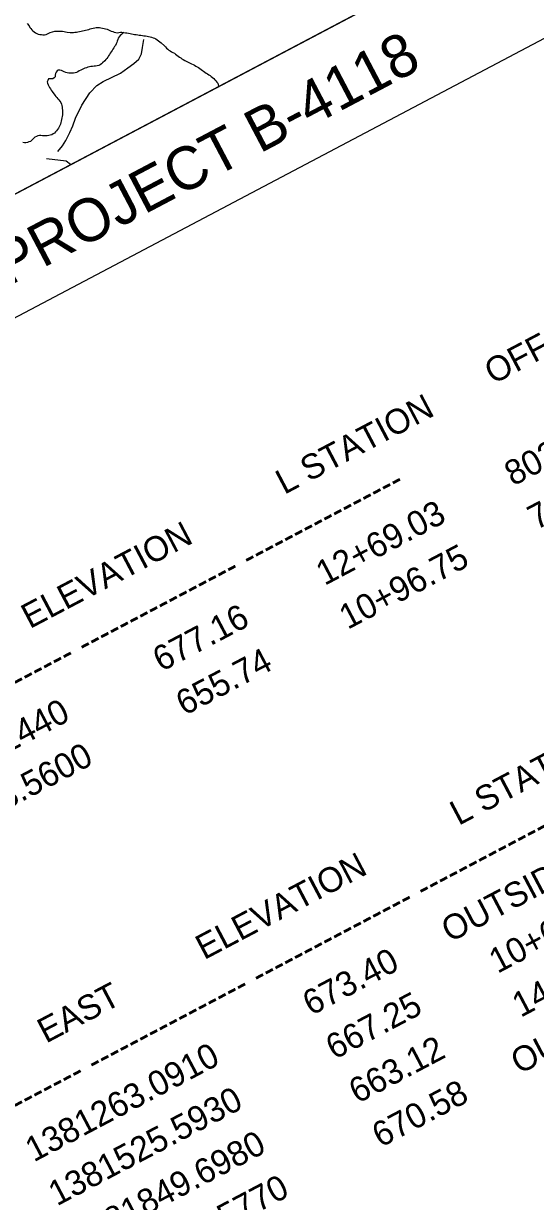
# Model space of a CAD drawing. Extents: x 1379448 to 1382868, y 593769 to 596827.
# Drawn here: x 1380243 to 1380457.9, y 594832.7 to 595326.7 of the extents above; entities that cross this region are included whole.
import ezdxf

# ---------------------------------------------------------------- set-up
doc = ezdxf.new("R2010")
doc.units = 0
for name, color, linetype in [('CTL Sheet Text', 7, 'Continuous'), ('Old_Level_1', 7, 'Continuous'), ('Old_Level_32', 7, 'Continuous'), ('Old_Level_35', 7, 'Continuous'), ('Old_Level_59', 7, 'Continuous'), ('Old_Level_62', 7, 'Continuous')]:
    doc.layers.add(name, color=color, linetype=linetype)

msp = doc.modelspace()

# ---------------------------------------------------------------- linework, layer by layer
at = {"layer": 'Old_Level_1'}
msp.add_line((1379782.59, 595014.48), (1380447.79, 595365.17), dxfattribs=at)
msp.add_lwpolyline([(1379782.59, 595014.48), (1380447.79, 595365.17), (1380469.23, 595324.5), (1379804.02, 594973.82)], close=True, dxfattribs=at)
at = {"layer": 'Old_Level_32'}
msp.add_lwpolyline([(1380262.66, 595267.57), (1380260.81, 595268.98), (1380252.6, 595269.97)], dxfattribs=at)
at = {"layer": 'Old_Level_35'}
msp.add_lwpolyline([(1380257.31, 595273.11), (1380259.38, 595275.46), (1380260.68, 595277.67), (1380262.44, 595281.04), (1380263.65, 595283.75), (1380264.74, 595286.99), (1380267.38, 595292.47), (1380270.76, 595297.66), (1380273.73, 595300.77), (1380276.44, 595302.45), (1380283.69, 595305.86), (1380286.74, 595308.2), (1380289.22, 595310), (1380291.42, 595311.73), (1380292.55, 595314.03), (1380292.98, 595316.7), (1380293.52, 595319.99)], dxfattribs=at)
at = {"layer": 'Old_Level_59'}
for points in [[(1380244.56, 595326.74), (1380245.35, 595325.71), (1380245.65, 595325.12), (1380246.05, 595324.6), (1380246.46, 595324.09), (1380246.91, 595323.6), (1380247.4, 595323.18), (1380247.97, 595322.83), (1380248.55, 595322.55), (1380249.18, 595322.31), (1380249.81, 595322.16), (1380250.47, 595322.08), (1380251.12, 595322.03), (1380251.78, 595322), (1380252.42, 595322.12), (1380253.02, 595322.4), (1380253.6, 595322.71), (1380254.19, 595323), (1380256.05, 595323.55), (1380256.71, 595323.58), (1380257.36, 595323.58), (1380258.02, 595323.56), (1380258.68, 595323.51), (1380259.34, 595323.46), (1380259.99, 595323.38), (1380260.63, 595323.26), (1380261.28, 595323.15), (1380262.59, 595322.97), (1380263.24, 595322.91), (1380263.9, 595322.95), (1380264.54, 595323.05), (1380265.19, 595323.16), (1380265.83, 595323.27), (1380266.48, 595323.4), (1380267.12, 595323.54), (1380267.76, 595323.68), (1380268.4, 595323.83), (1380269.04, 595323.97), (1380270.33, 595324.27), (1380270.94, 595324.49), (1380271.55, 595324.69), (1380272.2, 595324.82), (1380272.85, 595324.92), (1380273.51, 595325), (1380274.16, 595325.04)], [(1380274.16, 595325.04), (1380274.81, 595325.02), (1380275.46, 595324.95), (1380276.12, 595324.84), (1380276.76, 595324.7), (1380277.4, 595324.54), (1380278.02, 595324.32), (1380278.63, 595324.09), (1380279.2, 595323.77), (1380279.82, 595323.54), (1380280.44, 595323.33), (1380281.07, 595323.14), (1380281.71, 595322.99), (1380282.36, 595322.88), (1380282.99, 595322.95), (1380283.63, 595323.06), (1380284.29, 595323.05), (1380285.08, 595322.89)], [(1380285.08, 595322.89), (1380285.74, 595322.87), (1380286.39, 595322.77), (1380287.03, 595322.63), (1380287.67, 595322.48), (1380288.32, 595322.35), (1380288.96, 595322.24), (1380289.61, 595322.14), (1380290.26, 595322.05), (1380290.91, 595321.96), (1380291.56, 595321.87), (1380292.22, 595321.79), (1380292.86, 595321.69), (1380293.51, 595321.6), (1380294.17, 595321.5), (1380294.81, 595321.39), (1380295.45, 595321.28), (1380296.1, 595321.13), (1380296.73, 595320.95), (1380297.36, 595320.75), (1380297.97, 595320.52), (1380298.56, 595320.24), (1380299.12, 595319.88), (1380299.65, 595319.5), (1380300.17, 595319.1), (1380300.69, 595318.69), (1380302.12, 595317.38), (1380302.59, 595316.92), (1380303.04, 595316.44), (1380303.52, 595315.99), (1380304.03, 595315.59), (1380304.58, 595315.23), (1380305.15, 595314.9), (1380305.72, 595314.57), (1380306.28, 595314.23), (1380306.82, 595313.85), (1380307.35, 595313.47), (1380307.87, 595313.07), (1380308.4, 595312.68), (1380308.94, 595312.31), (1380309.49, 595311.95), (1380310.05, 595311.61), (1380310.62, 595311.28), (1380311.19, 595310.96), (1380311.77, 595310.64), (1380312.36, 595310.35), (1380312.94, 595310.06), (1380313.54, 595309.77), (1380314.13, 595309.49), (1380314.72, 595309.2), (1380315.3, 595308.9), (1380315.87, 595308.58), (1380316.42, 595308.22), (1380316.94, 595307.81), (1380319.64, 595305.96), (1380320.2, 595305.61), (1380320.75, 595305.26), (1380321.29, 595304.88), (1380321.81, 595304.48), (1380322.32, 595304.07), (1380322.81, 595303.62), (1380323.26, 595303.16), (1380323.73, 595302.68), (1380324.17, 595302.19), (1380324.52, 595301.65), (1380324.74, 595301.03), (1380324.9, 595300.39), (1380324.9, 595300.38)]]:
    msp.add_lwpolyline(points, dxfattribs=at)
at = {"layer": 'Old_Level_62'}
for points in [[(1380285.08, 595322.89), (1380284.57, 595322.49), (1380284.05, 595322.08), (1380283.55, 595321.66), (1380283.13, 595321.17), (1380282.75, 595320.62), (1380282.5, 595320.02), (1380282.32, 595319.39), (1380282.14, 595318.76), (1380281.89, 595318.15), (1380281.57, 595317.57), (1380281.22, 595317.02), (1380280.87, 595316.47), (1380280.5, 595315.92), (1380280.14, 595315.37), (1380279.77, 595314.83), (1380279.41, 595314.28), (1380279.04, 595313.74), (1380278.67, 595313.2), (1380278.3, 595312.66), (1380277.92, 595312.11), (1380277.53, 595311.59), (1380277.09, 595311.1), (1380276.17, 595310.21), (1380275.64, 595309.8), (1380275.1, 595309.44), (1380274.52, 595309.14), (1380273.89, 595308.93), (1380273.24, 595308.83), (1380272.59, 595308.8), (1380271.93, 595308.75), (1380271.29, 595308.63), (1380270.64, 595308.5), (1380270, 595308.35), (1380269.36, 595308.19), (1380268.73, 595308.01), (1380268.13, 595307.76), (1380267.54, 595307.46), (1380266.97, 595307.14), (1380266.39, 595306.82), (1380265.81, 595306.52), (1380265.21, 595306.25), (1380264.59, 595306.03), (1380263.95, 595305.91), (1380263.29, 595305.87), (1380262.63, 595305.86), (1380261.97, 595305.91), (1380261.33, 595306.01), (1380260.7, 595306.2), (1380260.08, 595306.43), (1380259.47, 595306.68), (1380258.88, 595306.96), (1380258.24, 595307.12), (1380257.58, 595307.17), (1380257.05, 595306.82), (1380256.63, 595306.31), (1380256.36, 595305.72), (1380256.29, 595305.06), (1380256.19, 595304.41), (1380255.83, 595303.88), (1380255.25, 595303.59), (1380254.6, 595303.53), (1380253.52, 595303.46), (1380253.13, 595302.89), (1380252.91, 595302.3), (1380253.04, 595301.69), (1380253.31, 595301.07), (1380253.63, 595300.47), (1380253.94, 595299.89), (1380254.28, 595299.32), (1380254.63, 595298.76), (1380254.99, 595298.22), (1380256.18, 595296.67), (1380256.59, 595296.16), (1380257.02, 595295.66), (1380257.44, 595295.15), (1380257.86, 595294.65), (1380258.26, 595294.13), (1380258.61, 595293.58), (1380258.87, 595292.97), (1380259.06, 595292.34), (1380259.15, 595291.69), (1380259.21, 595291.04), (1380259.28, 595290.38), (1380259.31, 595289.72), (1380259.32, 595289.07), (1380259.28, 595288.42), (1380259.2, 595287.76), (1380259.08, 595287.12), (1380258.95, 595286.47), (1380258.8, 595285.83), (1380258.63, 595285.2), (1380258.43, 595284.57), (1380258.2, 595283.95), (1380257.93, 595283.35), (1380257.62, 595282.77), (1380257.26, 595282.23), (1380256.84, 595281.72), (1380256.41, 595281.23), (1380255.95, 595280.75)], [(1380255.95, 595280.75), (1380255.4, 595280.4), (1380254.81, 595280.11), (1380254.19, 595279.89), (1380253.55, 595279.72), (1380252.9, 595279.65), (1380252.24, 595279.64), (1380251.59, 595279.66), (1380250.93, 595279.68), (1380250.27, 595279.7), (1380249.61, 595279.7), (1380248.97, 595279.64), (1380248.37, 595279.36), (1380247.78, 595279.05), (1380247.27, 595278.65), (1380246.82, 595278.16), (1380246.37, 595277.67), (1380245.85, 595277.29), (1380245.24, 595277.06), (1380244.6, 595276.87), (1380243.97, 595276.71), (1380243.31, 595276.71), (1380242.65, 595276.78)]]:
    msp.add_lwpolyline(points, dxfattribs=at)

# ---------------------------------------------------------------- texts
at = {"layer": 'CTL Sheet Text'}
for s, p in [('    POINT          DESC.           NORTH             EAST          ELEVATION           L STATION       OFFSET', (1379930, 594906.31)), ('1                     B4118-1      596251.6720     1381327.2440           677.16         12+69.03        802.13 LT', (1379949.43, 594869.45)), ('2                     B4118-2      594770.5120     1381808.5600           655.74         10+96.75        740.30 RT', (1379959.15, 594851.03)), ('------------ ---------------- ---------------- ---------------- ---------------- ---------------- ----------------', (1379939.72, 594887.88)), ('    POINT          DESC.           NORTH             EAST          ELEVATION           L STATION       OFFSET', (1380003.19, 594767.49)), ('3                        BL-3      595511.9450     1381263.0910           673.40      OUTSIDE PROJECT LIMITS                 ', (1380022.62, 594730.63)), ('4                        BL-4      595437.7990     1381525.5930           667.25         10+68.66         17.88 RT', (1380032.34, 594712.2)), ('------------ ---------------- ---------------- ---------------- ---------------- ---------------- ----------------', (1380012.9, 594749.06)), ('5                        BL-5      595615.1650     1381849.6980           663.12         14+30.97         13.34 RT', (1380042.05, 594693.77)), ('6                        BL-6      595829.4730     1381880.5770           670.58      OUTSIDE PROJECT LIMITS                 ', (1380051.77, 594675.34))]:
    msp.add_text(s, height=10.41667, rotation=27.7977, dxfattribs=at).set_placement(p)
at = {"layer": 'Old_Level_32'}
msp.add_text('VICINITY MAP SHOWING LOCATION OF PROJECT B-4118', height=18, rotation=27.7977, dxfattribs=at).set_placement((1379828.68, 595001.39))

doc.saveas('drawing.dxf')
